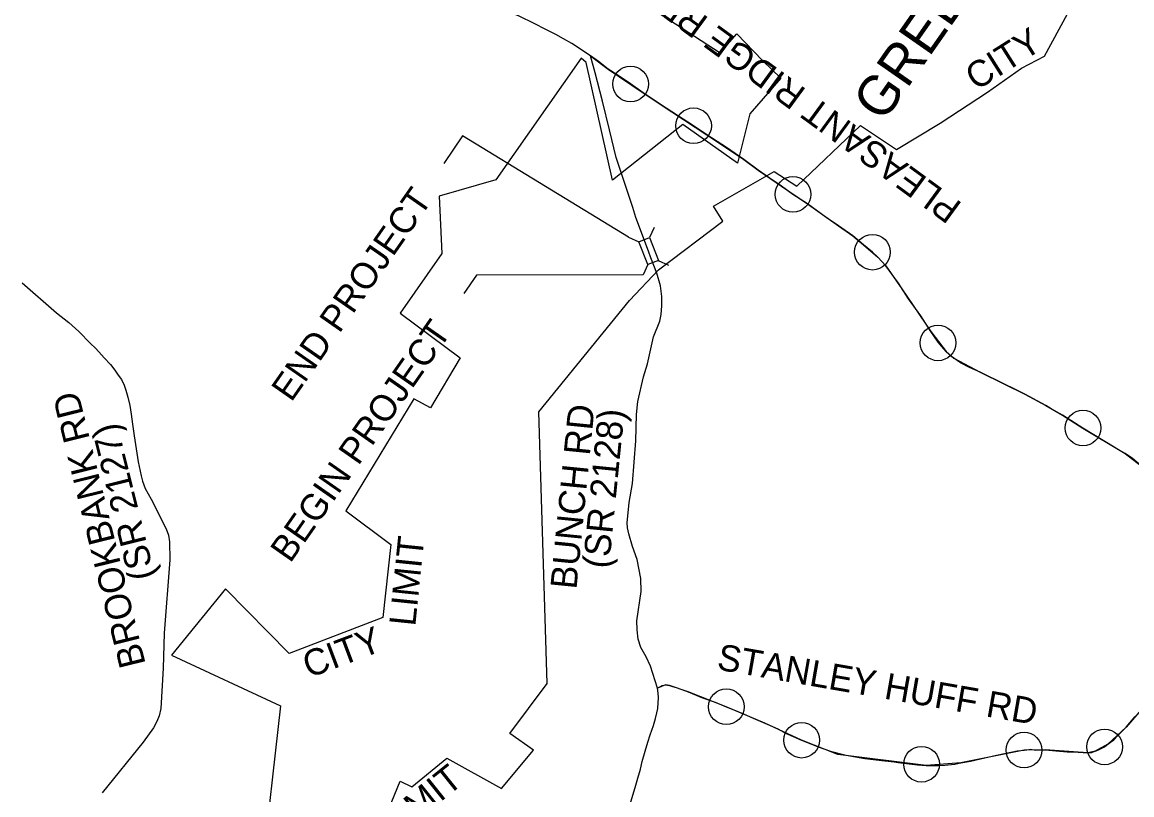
# Model space of a CAD drawing. Extents: x 1731327 to 1735374, y 884856 to 889832.
# Drawn here: x 1731364.4 to 1731582.7, y 885272.1 to 885424.2 of the extents above; entities that cross this region are included whole.
import ezdxf

# ---------------------------------------------------------------- set-up
doc = ezdxf.new("R2010")
doc.units = 0
for name, color, linetype in [('Exist Horizontal Alignment Point', 7, 'Continuous'), ('Exist Horizontal Baseline Alignment', 7, 'Continuous'), ('Exist Other Culture Located Object CELL', 7, 'Continuous'), ('Exist Other Culture Sign Text', 7, 'Continuous'), ('Exist Structure Major Deck Tunnel Box Culvert Text', 7, 'Continuous'), ('Exist Utilities Telephone UG Cable SUE', 7, 'Continuous')]:
    doc.layers.add(name, color=color, linetype=linetype)

msp = doc.modelspace()

# ---------------------------------------------------------------- linework, layer by layer
at = {"layer": 'Exist Horizontal Alignment Point'}
for p, q in [((1731483.75, 885381.89), (1731451.08, 885401.82)), ((1731486.64, 885374.49), (1731453.84, 885374.41)), ((1731486.64, 885374.49), (1731453.84, 885374.41))]:
    msp.add_line(p, q, dxfattribs=at)
at = {"layer": 'Exist Horizontal Baseline Alignment'}
for points in [[(1731476.24, 885417.55), (1731479.71, 885414.94), (1731486.6, 885410.31), (1731492.23, 885406.57), (1731499.17, 885402.03), (1731506.4, 885397.2), (1731509.21, 885395.1), (1731513.83, 885391.92), (1731518.95, 885388.42), (1731525.07, 885384.12), (1731527.85, 885382.18), (1731529.95, 885380.4), (1731532.78, 885377.96), (1731534.35, 885376.24), (1731537.51, 885371.75), (1731543.2, 885363.33), (1731546.2, 885359.37), (1731547.71, 885358.07), (1731552.92, 885355.3), (1731557.71, 885352.98), (1731561.67, 885350.98), (1731565.8, 885348.74), (1731569.08, 885346.84), (1731573.14, 885344.32), (1731581.43, 885339.32), (1731584.58, 885336.87)], [(1731476.24, 885417.55), (1731479.71, 885414.94), (1731486.6, 885410.31), (1731492.23, 885406.57), (1731499.17, 885402.03), (1731506.4, 885397.2), (1731509.21, 885395.1), (1731513.83, 885391.92), (1731518.95, 885388.42), (1731525.07, 885384.12), (1731527.85, 885382.18), (1731529.95, 885380.4), (1731532.78, 885377.96), (1731534.35, 885376.24), (1731537.51, 885371.75), (1731543.2, 885363.33), (1731546.2, 885359.37), (1731547.71, 885358.07), (1731552.92, 885355.3), (1731557.71, 885352.98), (1731561.67, 885350.98), (1731565.8, 885348.74), (1731569.08, 885346.84), (1731573.14, 885344.32), (1731581.43, 885339.32), (1731584.58, 885336.87)], [(1731586.71, 885291.26), (1731581.61, 885285.42), (1731578.05, 885282.09), (1731575.51, 885280.75), (1731574.13, 885280.37), (1731572.2, 885280.5), (1731565.72, 885280.96), (1731561.54, 885280.93), (1731549.13, 885278.42), (1731542.26, 885277.88), (1731524.9, 885280.07), (1731517.79, 885282.88), (1731510.54, 885286.23), (1731502.97, 885289.46), (1731495.44, 885292.37), (1731491.77, 885293.62), (1731491, 885293.75), (1731489.41, 885293.12)], [(1731586.71, 885291.26), (1731581.61, 885285.42), (1731578.05, 885282.09), (1731575.51, 885280.75), (1731574.13, 885280.37), (1731572.2, 885280.5), (1731565.72, 885280.96), (1731561.54, 885280.93), (1731549.13, 885278.42), (1731542.26, 885277.88), (1731524.9, 885280.07), (1731517.79, 885282.88), (1731510.54, 885286.23), (1731502.97, 885289.46), (1731495.44, 885292.37), (1731491.77, 885293.62), (1731491, 885293.75), (1731489.41, 885293.12)]]:
    msp.add_lwpolyline(points, dxfattribs=at)
for centre in [(1731484.14, 885412.04), (1731496.52, 885403.81), (1731516.08, 885390.31), (1731531.71, 885378.93), (1731544.61, 885361.08), (1731573.14, 885344.32), (1731502.97, 885289.46), (1731517.79, 885282.88), (1731561.54, 885280.93), (1731577.39, 885281.56), (1731541.38, 885278.15)]:
    msp.add_circle(centre, 3.51, dxfattribs=at)
at = {"layer": 'Exist Other Culture Located Object CELL'}
for points in [[(1731476.24, 885417.55), (1731472.57, 885419.98), (1731470.96, 885420.95), (1731469.44, 885421.77), (1731467.47, 885422.77), (1731465.14, 885423.93), (1731462.23, 885425.37), (1731459.79, 885426.39), (1731454.47, 885428.81), (1731451.85, 885429.73), (1731448.76, 885431.3), (1731443.57, 885433.89), (1731441.26, 885435.08), (1731437.37, 885437.2), (1731432.96, 885439.62), (1731430.84, 885440.83), (1731429.21, 885441.78), (1731417.3, 885448.65)], [(1731487.68, 885379.15), (1731485.2, 885385.75), (1731484.57, 885387.71), (1731481.3, 885397.54), (1731479.98, 885403.04), (1731478.58, 885408.67), (1731477.15, 885414.25), (1731476.24, 885417.55)], [(1731509.21, 885395.1), (1731506.4, 885397.2), (1731502.99, 885399.53), (1731499.17, 885402.03), (1731496.52, 885403.81), (1731492.23, 885406.57), (1731489.84, 885408.15), (1731486.6, 885410.31), (1731484.14, 885412.04), (1731481.5, 885413.83), (1731479.71, 885414.94), (1731477.8, 885416.46), (1731476.24, 885417.55)], [(1731565.8, 885348.74), (1731561.67, 885350.98), (1731559.63, 885352.04), (1731557.71, 885352.98), (1731552.92, 885355.3), (1731550.78, 885356.25), (1731549.07, 885357.18), (1731547.71, 885358.07), (1731547.1, 885358.55), (1731546.63, 885359), (1731546.2, 885359.37), (1731545.3, 885360.43), (1731544.67, 885361.19), (1731543.2, 885363.33), (1731541.23, 885366.41), (1731538.82, 885369.74), (1731536.83, 885372.86), (1731534.35, 885376.24), (1731532.78, 885377.96), (1731531.71, 885378.93), (1731529.95, 885380.4), (1731527.85, 885382.18), (1731525.07, 885384.12), (1731522.63, 885385.75), (1731518.95, 885388.42), (1731516.08, 885390.31), (1731513.83, 885391.92), (1731511.42, 885393.57), (1731509.21, 885395.1)], [(1731489.41, 885293.12), (1731488.06, 885297.46), (1731487.18, 885299.27), (1731486.14, 885301.13), (1731485.66, 885302.76), (1731485.41, 885304.6), (1731485.38, 885306.39), (1731486.22, 885312.12), (1731486.14, 885314.7), (1731485.41, 885318.47), (1731484.51, 885321.03), (1731483.79, 885323.52), (1731483.54, 885324.67), (1731483.48, 885325.64), (1731483.89, 885329.63), (1731484.52, 885333.41), (1731485.18, 885341.79), (1731485.29, 885347.01), (1731485.59, 885349.54), (1731486.68, 885354.41), (1731487.44, 885356.98), (1731488.65, 885362.24), (1731489.87, 885365.36), (1731490.13, 885366.64), (1731490.29, 885368.34), (1731490.3, 885370.24), (1731490.02, 885372.29), (1731489.28, 885374.78), (1731488.15, 885377.85), (1731487.68, 885379.15)], [(1731364.45, 885372.91), (1731371.22, 885367.01), (1731373.62, 885365.08), (1731375.6, 885363.3), (1731377.9, 885360.96), (1731378.85, 885360.02), (1731379.53, 885359.29), (1731380.58, 885358.11), (1731381.84, 885356.81), (1731382.7, 885355.73), (1731383.35, 885354.73), (1731383.96, 885353.85), (1731384.52, 885352.77), (1731384.87, 885351.79), (1731385.26, 885350.41), (1731385.6, 885348.75), (1731385.87, 885347.02), (1731386.15, 885345.08), (1731386.48, 885342.79), (1731386.9, 885340.23), (1731387.27, 885337.66), (1731387.86, 885334.91)], [(1731573.14, 885344.32), (1731569.08, 885346.84), (1731566.89, 885348.11), (1731565.8, 885348.74)], [(1731584.58, 885336.87), (1731582.91, 885338.32), (1731581.43, 885339.32), (1731579.58, 885340.37), (1731573.14, 885344.32)], [(1731387.86, 885334.91), (1731388.13, 885333.87), (1731388.67, 885332.43), (1731389.82, 885330.34), (1731392.77, 885324.45), (1731393.25, 885323.24), (1731393.46, 885321.94), (1731393.48, 885318.36), (1731392.41, 885303.94), (1731392.21, 885297.04), (1731391.7, 885289.14), (1731391.37, 885287.66), (1731390.94, 885286.55), (1731390.29, 885285.3), (1731388.28, 885282.48), (1731380.16, 885272.52)], [(1731488.01, 885283.93), (1731488.63, 885285.79), (1731489.06, 885287.17), (1731489.33, 885288.25), (1731489.47, 885289.09), (1731489.61, 885291.26), (1731489.58, 885292.13), (1731489.41, 885293.12)], [(1731489.41, 885293.12), (1731490.33, 885293.62), (1731491, 885293.75), (1731491.77, 885293.62), (1731492.37, 885293.46), (1731493.33, 885293.2), (1731495.44, 885292.37), (1731498.28, 885291.19), (1731500.76, 885290.34), (1731502.97, 885289.46), (1731504.76, 885288.72), (1731506.46, 885288.02), (1731508.7, 885287.01), (1731510.54, 885286.23), (1731511.95, 885285.62), (1731513.23, 885285.02), (1731514.62, 885284.27), (1731516.1, 885283.61), (1731517.79, 885282.88), (1731519.05, 885282.35), (1731521.06, 885281.55), (1731522.13, 885281.15), (1731523.49, 885280.75), (1731526.57, 885279.92), (1731530.19, 885279.29), (1731533.55, 885278.85), (1731535.96, 885278.61), (1731536.77, 885278.52), (1731540.55, 885278.05), (1731542.26, 885277.88), (1731543.33, 885277.9), (1731544.63, 885277.89), (1731545.99, 885277.98), (1731547.9, 885278.19), (1731549.13, 885278.42), (1731551.03, 885278.77), (1731553.8, 885279.43), (1731556.1, 885279.96), (1731558.92, 885280.53), (1731560.2, 885280.77), (1731561.54, 885280.93), (1731562.1, 885281), (1731562.82, 885281.08), (1731563.87, 885280.93), (1731565.72, 885280.96), (1731568.51, 885280.74), (1731570.03, 885280.59), (1731572.2, 885280.5), (1731574.13, 885280.37), (1731574.85, 885280.48), (1731575.11, 885280.57), (1731575.51, 885280.75), (1731576.06, 885280.92), (1731576.56, 885281.16), (1731577.39, 885281.56), (1731578.05, 885282.09), (1731578.58, 885282.51), (1731579.21, 885282.98), (1731580.09, 885283.87), (1731581.61, 885285.42), (1731583.39, 885287.53)], [(1731484.17, 885270.72), (1731485.07, 885273.54), (1731485.58, 885275.43), (1731486.06, 885277.15), (1731486.44, 885278.66), (1731487.03, 885280.74), (1731487.53, 885282.49), (1731488.01, 885283.93)]]:
    msp.add_lwpolyline(points, dxfattribs=at)
at = {"layer": 'Exist Other Culture Sign Text'}
for points in [[(1731436.56, 885269.4), (1731438.83, 885274.8), (1731441.07, 885273.73), (1731448, 885279.37), (1731458.75, 885273.36), (1731465.04, 885280.94), (1731460.35, 885284.21), (1731467.7, 885294.03), (1731466.12, 885347.48), (1731483.94, 885369.44), (1731489.63, 885375.45), (1731502.31, 885385.05), (1731500.42, 885387.96), (1731512.4, 885394.83), (1731516.87, 885391.9), (1731529.38, 885403.84), (1731536.47, 885399.16), (1731545.02, 885404.34), (1731554.34, 885410.44), (1731561.05, 885415.18), (1731565.57, 885417.53), (1731574.63, 885434.26), (1731585.3, 885451.43)], [(1731478.04, 885433.68), (1731501.75, 885418.14), (1731505.04, 885421.89), (1731510.11, 885416.67), (1731513.7, 885413.16), (1731507.57, 885406.16), (1731505.2, 885396.45), (1731494.44, 885404.05), (1731480.55, 885393.11), (1731475.43, 885416.29), (1731474.4, 885417.13), (1731457.63, 885393.16), (1731446.45, 885389.99), (1731447, 885378.64), (1731438.81, 885366.91), (1731450.64, 885358.16), (1731444.76, 885348.3), (1731441.51, 885350.07), (1731428.12, 885328.02), (1731436.94, 885321.37), (1731435.38, 885307), (1731416.97, 885299.91), (1731404.43, 885312.65), (1731393.84, 885299.61), (1731415.28, 885289.63), (1731411.56, 885256.44)]]:
    msp.add_lwpolyline(points, dxfattribs=at)
at = {"layer": 'Exist Structure Major Deck Tunnel Box Culvert Text'}
for points in [[(1731483.75, 885381.89), (1731451.08, 885401.82), (1731447.38, 885396.41)], [(1731486.64, 885374.49), (1731453.84, 885374.41), (1731451.34, 885370.83)]]:
    msp.add_lwpolyline(points, dxfattribs=at)
at = {"layer": 'Exist Utilities Telephone UG Cable SUE'}
for p, q in [((1731488.76, 885383.82), (1731487.87, 885381.8)), ((1731483.75, 885381.89), (1731485.76, 885380.99)), ((1731489.59, 885377.29), (1731491.61, 885376.4)), ((1731487.53, 885376.5), (1731486.64, 885374.49))]:
    msp.add_line(p, q, dxfattribs=at)
msp.add_lwpolyline([(1731487.87, 885381.8), (1731489.6, 885377.3), (1731487.5, 885376.49), (1731485.76, 885380.99)], close=True, dxfattribs=at)

# ---------------------------------------------------------------- texts
at = {"layer": 'Exist Structure Major Deck Tunnel Box Culvert Text'}
for s, height, rotation, p in [('GREENSBORO', 7.852, 55.0911, (1731533.84, 885404.27)), ('PLEASANT RIDGE RD', 5.163, 143.8218, (1731549.57, 885388.45)), ('CITY', 5.163, 32.3223, (1731552.13, 885410.62)), ('END PROJECT', 5.163, 55.0911, (1731417.39, 885349.26)), ('BEGIN PROJECT', 5.163, 55.0911, (1731417.18, 885317.57)), ('BROOKBANK RD', 5.163, 103.9154, (1731388.77, 885297.86)), ('BUNCH RD', 5.163, 84.308, (1731473.48, 885312.46)), ('(SR 2128)', 5.163, 84.308, (1731479.85, 885316.54)), ('(SR 2127)', 5.163, 103.9154, (1731390.63, 885315.06)), ('LIMIT', 5.163, 84.1349, (1731441.77, 885305.19)), ('CITY', 5.163, 20.5588, (1731420.85, 885295.05)), ('STANLEY HUFF RD', 5.163, 350.098, (1731500.95, 885296.82)), ('LIMIT', 5.163, 38.7031, (1731437.7, 885263.41))]:
    msp.add_text(s, height=height, rotation=rotation, dxfattribs=at).set_placement(p)

doc.saveas('drawing.dxf')
